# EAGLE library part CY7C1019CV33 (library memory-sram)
128K x 8 Static RAM 10ns Source: Cypress CYP05780611.pdf
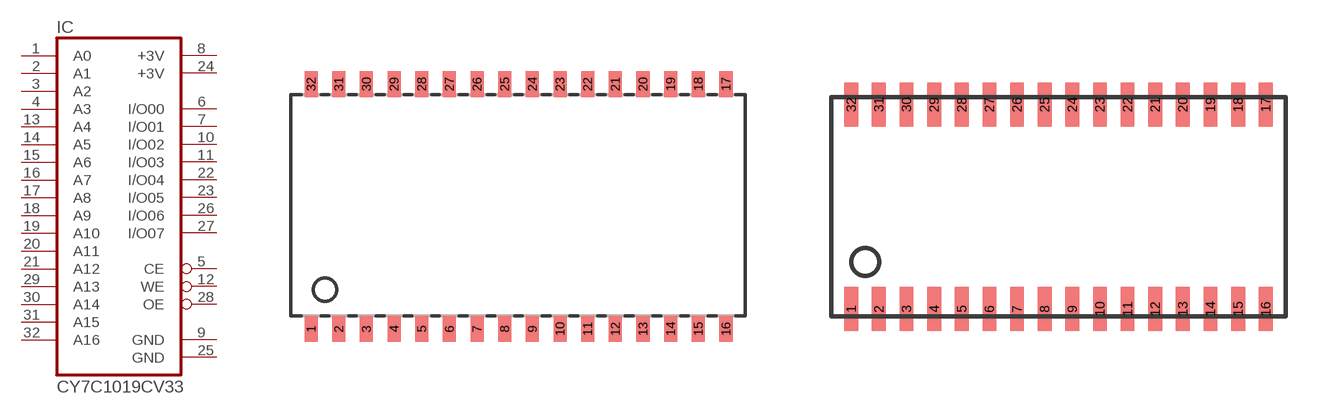
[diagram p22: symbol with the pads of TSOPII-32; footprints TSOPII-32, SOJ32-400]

Designator prefix IC

## CY7C1019CV33ZXC, CY7C1019CV33-10ZXC, CY7C1019CV33-12ZXC, CY7C1019CV33-15ZXC  [TSOPII-32]
1  A0  in
2  A1  in
3  A2  in
4  A3  in
5  CE
6  I/O00
7  I/O01
8  +3V  pwr
9  GND  pwr
10  I/O02
11  I/O03
12  WE  in
13  A4  in
14  A5  in
15  A6  in
16  A7  in
17  A8  in
18  A9  in
19  A10  in
20  A11  in
21  A12  in
22  I/O04
23  I/O05
24  +3V  pwr
25  GND  pwr
26  I/O06
27  I/O07
28  OE  in
29  A13  in
30  A14  in
31  A15  in
32  A16  in

## CY7C1019CV33-10VC, CY7C1019CV33-12VC, CY7C1019CV33-15VC  [SOJ32-400]
Pads as for TSOPII-32

## CY7C1019CV33-12BVXI  [VFBGA48]
A2  OE  in
A3  A2  in
A4  A6  in
A5  A7  in
B1  I/O00
B3  A1  in
B4  A5  in
B5  CE
B6  I/O07
C1  I/O01
C3  A0  in
C4  A4  in
C6  I/O06
D1  GND  pwr
D4  A3  in
D6  +3V  pwr
E1  +3V  pwr
E6  GND  pwr
F1  I/O02
F3  A14  in
F4  A11  in
F5  I/O04
F6  I/O05
G1  I/O03
G3  A15  in
G4  A12  in
G5  WE  in
G6  A8  in
H2  A10  in
H3  A16  in
H4  A13  in
H5  A9  in

## Footprint TSOPII-32 (pad centres in mm)
32-pin TSOP II (51-85095) Source: Cypress CYP05780611.pdf
smd 0.6 x 1.2: 1 -9.525,-5.627; 2 -8.255,-5.627; 3 -6.985,-5.627; 4 -5.715,-5.627; 5 -4.445,-5.627; 6 -3.175,-5.627; 7 -1.905,-5.627; 8 -0.635,-5.627; 9 0.635,-5.627; 10 1.905,-5.627; 11 3.175,-5.627; 12 4.445,-5.627; 13 5.715,-5.627; 14 6.985,-5.627; 15 8.255,-5.627; 16 9.525,-5.627; 17 9.525,5.629; 18 8.255,5.629; 19 6.985,5.629; 20 5.715,5.629; 21 4.445,5.629; 22 3.175,5.629; 23 1.905,5.629; 24 0.635,5.629; 25 -0.635,5.629; 26 -1.905,5.629; 27 -3.175,5.629; 28 -4.445,5.629; 29 -5.715,5.629; 30 -6.985,5.629; 31 -8.255,5.629; 32 -9.525,5.629

## Footprint SOJ32-400 (pad centres in mm)
32-pin (400-Mil) Molded SOJ (51-85033) Source:
smd 0.635 x 2.032: 1 -9.525,-4.699; 2 -8.255,-4.699; 3 -6.985,-4.699; 4 -5.715,-4.699; 5 -4.445,-4.699; 6 -3.175,-4.699; 7 -1.905,-4.699; 8 -0.635,-4.699; 9 0.635,-4.699; 10 1.905,-4.699; 11 3.175,-4.699; 12 4.445,-4.699; 13 5.715,-4.699; 14 6.985,-4.699; 15 8.255,-4.699; 16 9.525,-4.699; 17 9.525,4.699; 18 8.255,4.699; 19 6.985,4.699; 20 5.715,4.699; 21 4.445,4.699; 22 3.175,4.699; 23 1.905,4.699; 24 0.635,4.699; 25 -0.635,4.699; 26 -1.905,4.699; 27 -3.175,4.699; 28 -4.445,4.699; 29 -5.715,4.699; 30 -6.985,4.699; 31 -8.255,4.699; 32 -9.525,4.699

## Footprint VFBGA48 (pad centres in mm)
48-ball VFBGA (6 x 8 x 1 mm) (51-85150) Source: Cypress CYP05780611.pdf
smd 0.45 x 0.45: A1 -1.875,2.625; A2 -1.125,2.625; A3 -0.375,2.625; A4 0.375,2.625; A5 1.125,2.625; A6 1.875,2.625; B1 -1.875,1.875; B2 -1.125,1.875; B3 -0.375,1.875; B4 0.375,1.875; B5 1.125,1.875; B6 1.875,1.875; C1 -1.875,1.125; C2 -1.125,1.125; C3 -0.375,1.125; C4 0.375,1.125; C5 1.125,1.125; C6 1.875,1.125; D1 -1.875,0.375; D2 -1.125,0.375; D3 -0.375,0.375; D4 0.375,0.375; D5 1.125,0.375; D6 1.875,0.375; E1 -1.875,-0.375; E2 -1.125,-0.375; E3 -0.375,-0.375; E4 0.375,-0.375; E5 1.125,-0.375; E6 1.875,-0.375; F1 -1.875,-1.125; F2 -1.125,-1.125; F3 -0.375,-1.125; F4 0.375,-1.125; F5 1.125,-1.125; F6 1.875,-1.125; G1 -1.875,-1.875; G2 -1.125,-1.875; G3 -0.375,-1.875; G4 0.375,-1.875; G5 1.125,-1.875; G6 1.875,-1.875; H1 -1.875,-2.625; H2 -1.125,-2.625; H3 -0.375,-2.625; H4 0.375,-2.625; H5 1.125,-2.625; H6 1.875,-2.625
